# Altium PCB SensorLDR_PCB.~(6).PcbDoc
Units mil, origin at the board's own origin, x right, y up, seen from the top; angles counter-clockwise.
Board outline 6000 x 4000 mil, 2 copper layers (Top Layer, Bottom Layer); 19 components, 11 nets, 54 pads, 0 vias.
Unrouted connection lines stored in the file: 35.
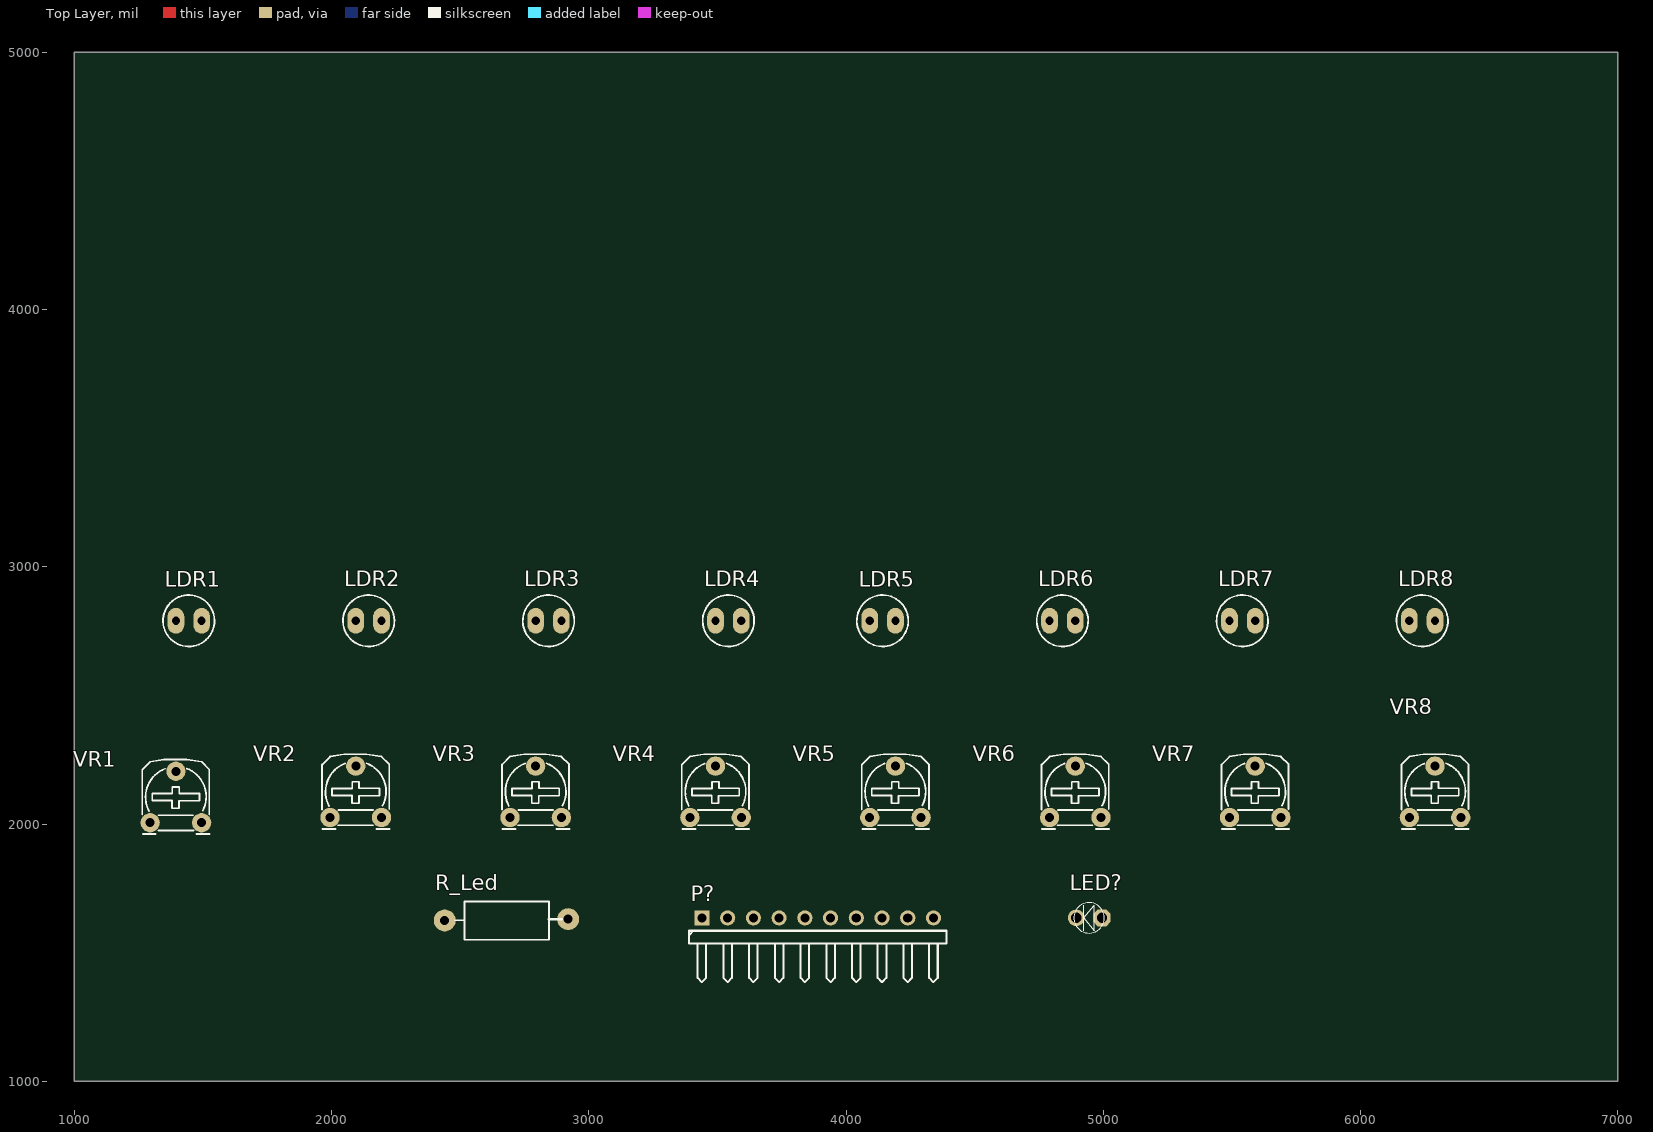
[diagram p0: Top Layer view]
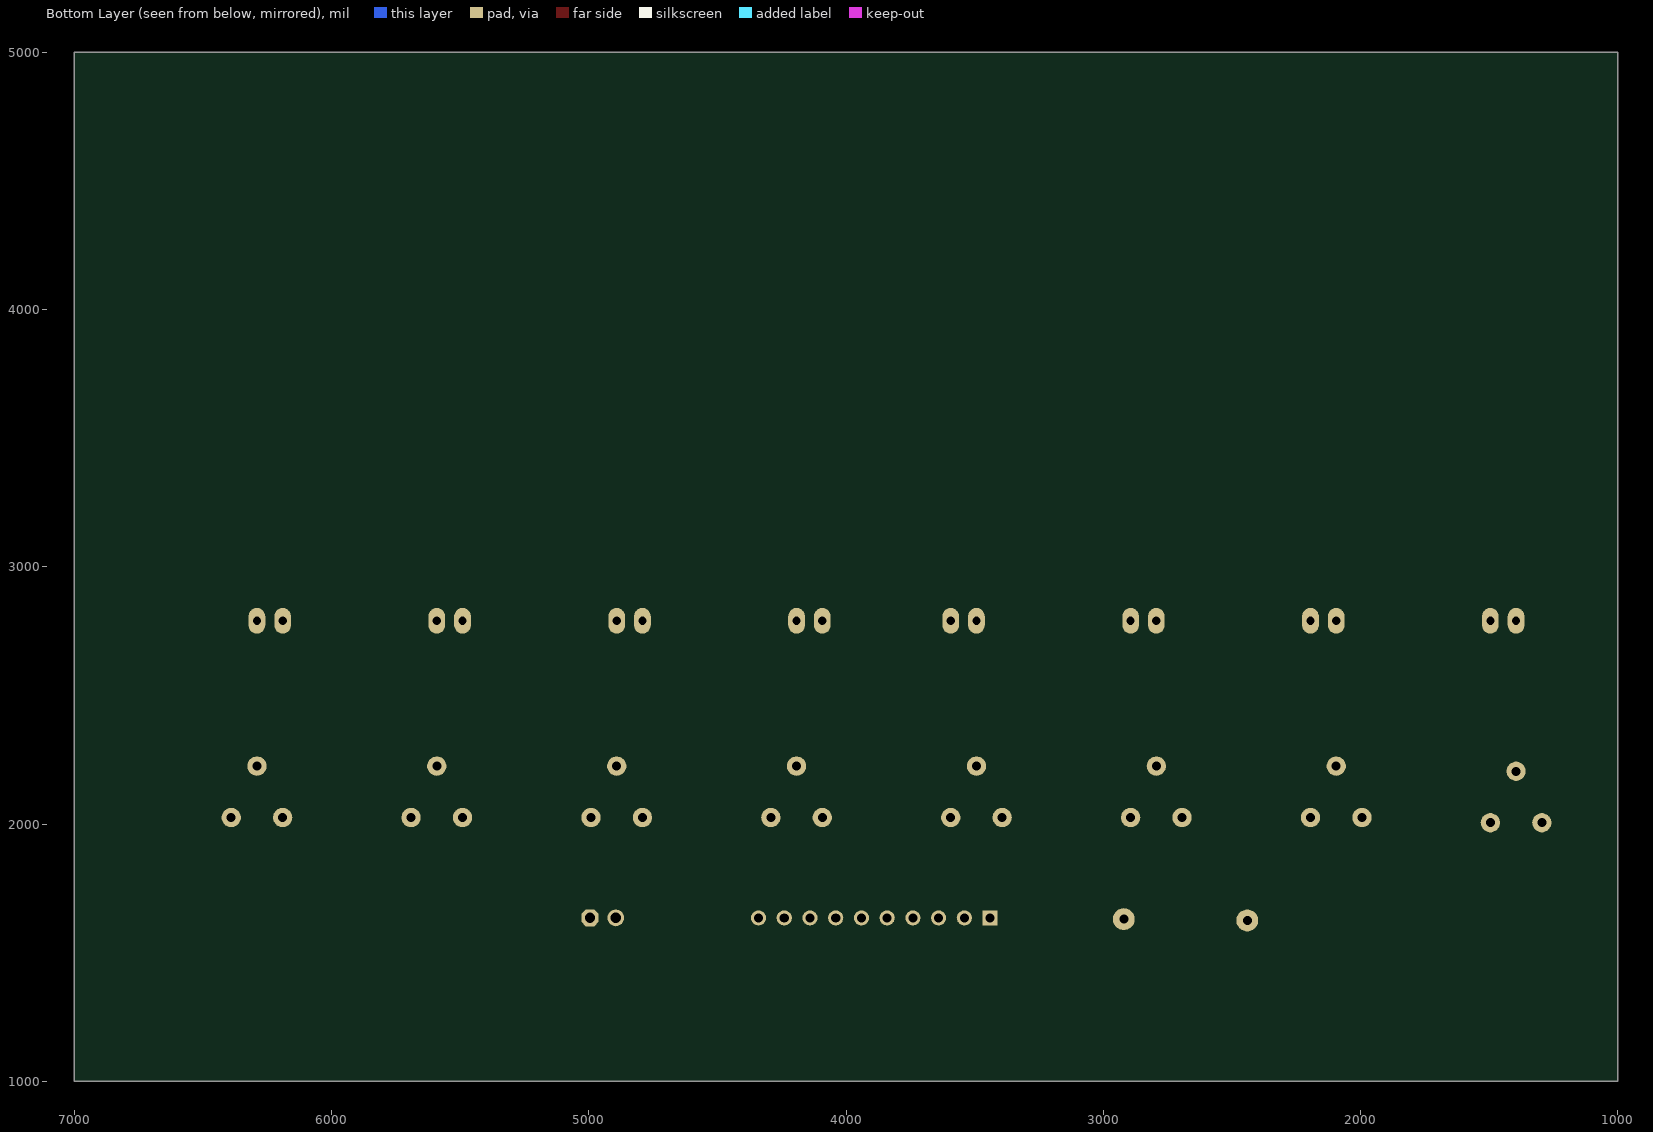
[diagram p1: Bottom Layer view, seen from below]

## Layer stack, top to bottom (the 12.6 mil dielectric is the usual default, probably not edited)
Top Solder: solder mask 0.4, Solder Resist, Dk 3.5
Top Layer: signal copper 1.4
Dielectric 1: dielectric 12.6, FR-4, Dk 4.8
Bottom Layer: signal copper 1.4
Bottom Solder: solder mask 0.4, Solder Resist, Dk 3.5

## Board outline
1000,1000 7000,1000 7000,5000 1000,5000

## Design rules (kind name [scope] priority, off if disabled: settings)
Clearance [All] p1: gap=10 ignorepadtopadclearanceinfootprint=FALSE except(0: Arc-Hole Track-Hole SMDPad-Hole THPad-Hole Via-Hole Fill-Hole Poly-Hole Region-Hole Text-Hole)
PolygonConnect [All] p1: connectstyle=Relief reliefconductorwidth=10 reliefentries=4 polygonreliefangle="90 Angle" airgapwidth=10
RoomDefinition SensorLDR [InComponentClass('SensorLDR')] p1: confinementstyle=ConfineIn formatcopy=TRUE lockcomponents=FALSE outline 7045,1060 8080,1060 8080,2180 7045,2180
RoutingVias [All] p1: holewidth=28 width=50 viastyle="Through Hole" minholewidth=28 minwidth=50 maxholewidth=28 maxwidth=50
SolderMaskExpansion [All] p1: expansion=4
Width [All] p1: maxlimit=10 minlimit=10 preferedwidth=10
30 further rules are at their usual default settings.

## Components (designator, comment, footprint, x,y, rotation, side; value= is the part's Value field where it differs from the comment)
LDR1 "LDR" CDS 1495,2790 r180 top
LDR2 "LDR" CDS 2194.29,2790 r180 top
LDR3 "LDR" CDS 2893.57,2790 r180 top
LDR4 "LDR" CDS 3592.86,2790 r180 top
LDR5 "LDR" CDS 4092.14,2790 r0 top
LDR6 "LDR" CDS 4791.43,2790 r0 top
LDR7 "LDR" CDS 5490.71,2790 r0 top
LDR8 "LDR" CDS 6190,2790 r0 top
LED? "LED" LED-3MM-YELLOW 4995,1635 r180 top value="LED 3 ly Single Colour"
P? "Header 10H" HDR1X10H 3440,1635 r0 top
R_Led "Res" RES-1/2W 2700,1625 r180 top
VR1 "50K" VR-S2 1295,2005 r0 top value="Volume 50k"
VR2 "50K" VR-S2 1994.29,2025 r0 top value="Volume 50k"
VR3 "50K" VR-S2 2693.57,2025 r0 top value="Volume 50k"
VR4 "50K" VR-S2 3392.86,2025 r0 top value="Volume 50k"
VR5 "50K" VR-S2 4092.14,2025 r0 top value="Volume 50k"
VR6 "50K" VR-S2 4791.43,2025 r0 top value="Volume 50k"
VR7 "50K" VR-S2 5490.71,2025 r0 top value="Volume 50k"
VR8 "50K" VR-S2 6190,2025 r0 top value="Volume 50k"

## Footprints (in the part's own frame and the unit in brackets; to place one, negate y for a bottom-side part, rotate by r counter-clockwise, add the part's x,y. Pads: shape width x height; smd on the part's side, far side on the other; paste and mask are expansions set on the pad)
CDS [mil] "QUANG TRO"
  oval 65x100 hole 32: 1(0,0) 2(100,0)
  silkscreen extent -50,-100 150,100, body extent -53,-80 153,89, height 138
HDR1X10H [mm] "Connector; Header; 10 Position; Right Angle"
  rect 1.5x1.5 hole 0.9: 1(0,0)
  round 1.5 hole 0.9: 2(2.54,0) 3(5.08,0) 4(7.62,0) 5(10.16,0) 6(12.7,0) 7(15.24,0) 8(17.78,0) 9(20.32,0) 10(22.86,0)
  silkscreen extent -1.27,-6.35 24.13,-1.27
LED-3MM-YELLOW [mil]
  oct 65x65 hole 40: 1(0,0)
  round 65 hole 40: 2(100,0)
  silkscreen extent -9,-59 109,59, body extent -27,-77 117,80, height 181
RES-1/2W [mil]
  round 85 hole 35: 1(-220,-5) 2(260,0)
  silkscreen extent -195,-74 221,75, body extent -230,-60 270,56, height 121
VR-S2 [mil] "Resistor Variable"
  round 75 hole 35: 1(0,0) 2(100,200) 3(200,0)
  silkscreen extent -31,-44 231,246, body extent -87,-30 307,372, height 165

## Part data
LDR1 LDR2 LDR3 LDR4 LDR5 LDR6 LDR7 LDR8: "Quang Tro"
LED?: "LED Single colour Green and Red"
P?: "Header, 10-Pin, Right Angle"
R_Led: Manufacturer="Generic Components"
VR1 VR2 VR3 VR4 VR5 VR6 VR7 VR8: library part VR-S, "Var Resistor"

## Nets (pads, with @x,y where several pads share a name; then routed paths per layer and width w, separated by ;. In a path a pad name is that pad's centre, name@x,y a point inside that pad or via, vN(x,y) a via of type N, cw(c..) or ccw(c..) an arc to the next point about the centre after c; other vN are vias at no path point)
GND: LDR1.1 LDR2.1 LDR3.1 LDR4.1 LDR5.1 LDR6.1 LDR7.1 LDR8.1 P?.2 R_Led.2
NetLED?_2: LED?.2 R_Led.1
S1: LDR1.2 P?.3 VR1.2
S2: LDR2.2 P?.4 VR2.2
S3: LDR3.2 P?.5 VR3.2
S4: LDR4.2 P?.6 VR4.2
S5: LDR5.2 P?.7 VR5.2
S6: LDR6.2 P?.8 VR6.2
S7: LDR7.2 P?.9 VR7.2
S8: LDR8.2 P?.10 VR8.2
VCC: LED?.1 P?.1 VR1.1 VR2.1 VR3.1 VR4.1 VR5.1 VR6.1 VR7.1 VR8.1
pads on no net: VR1.3 VR2.3 VR3.3 VR4.3 VR5.3 VR6.3 VR7.3 VR8.3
